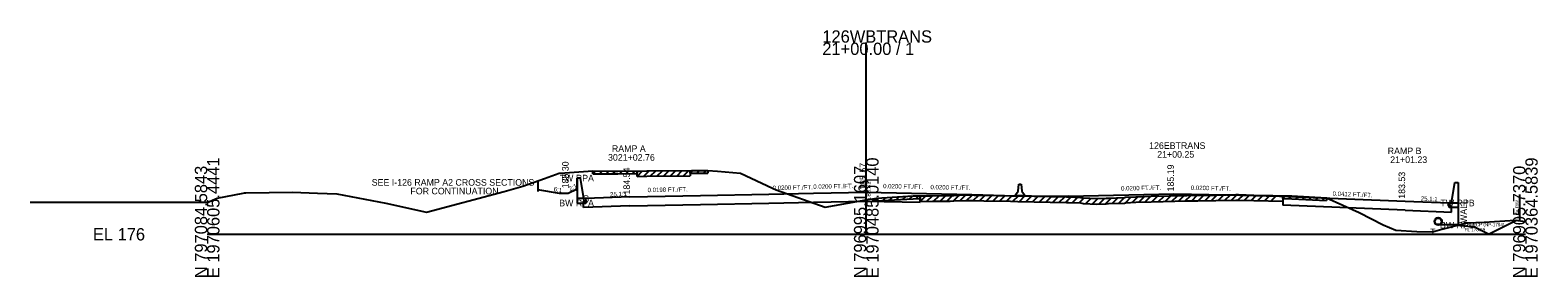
# Model space of a CAD drawing. Extents: x -6494 to 1970605, y -10 to 798140.
# Drawn here: x 959.7 to 1302.8, y 3490.3 to 3546.5 of the extents above; entities that cross this region are included whole.
import ezdxf

# ---------------------------------------------------------------- set-up
doc = ezdxf.new("R2010")
doc.units = 0
for name, color, linetype in [('Default', 7, 'Continuous'), ('RD_EX_SU_Misc_TxCode', 7, 'Continuous'), ('RD_GPK_XS_Cell', 7, 'Continuous'), ('RD_Sketch1', 7, 'Continuous'), ('RD_XS_Base', 7, 'Continuous'), ('RD_XS_Box', 7, 'Continuous'), ('RD_XS_EwShp', 7, 'Continuous'), ('RD_XS_ExGround', 7, 'Continuous'), ('RD_XS_ExPaveRet', 7, 'Continuous'), ('RD_XS_ExRW', 7, 'Continuous'), ('RD_XS_MedBWall', 7, 'Continuous'), ('RD_XS_Misc_Line', 7, 'Continuous'), ('RD_XS_Pave', 7, 'Continuous'), ('RD_XS_PaveOvlay', 7, 'Continuous'), ('RD_XS_PaveShd', 7, 'Continuous'), ('RD_XS_Pipe', 7, 'Continuous'), ('RD_XS_TieSlope', 7, 'Continuous'), ('RD_XS_TX_Elev_EX', 7, 'Continuous'), ('RD_XS_TX_Elev_PR', 7, 'Continuous'), ('RD_XS_TX_Misc', 7, 'Continuous'), ('RD_XS_TX_Notes', 7, 'Continuous'), ('RD_XS_TX_Profile', 7, 'Continuous'), ('RD_XS_TX_Slope', 7, 'Continuous'), ('RD_XS_TX_Station', 7, 'Continuous')]:
    doc.layers.add(name, color=color, linetype=linetype)

msp = doc.modelspace()

# ---------------------------------------------------------------- linework, layer by layer
at = {"layer": 'Default'}
for p, q in [((1184.58, 3509.84), (1184.75, 3511.43)), ((1184.75, 3511.43), (1185.25, 3511.43)), ((1185.25, 3511.43), (1185.42, 3509.84)), ((1184, 3509.01), (1184.58, 3509.84)), ((1184, 3508.76), (1184, 3509.01)), ((1186, 3508.76), (1184, 3508.76)), ((1185.42, 3509.84), (1186, 3509.01)), ((1186, 3509.01), (1186, 3508.76))]:
    msp.add_line(p, q, dxfattribs=at)
at = {"layer": 'RD_GPK_XS_Cell'}
for p, q in [((1150, 3500), (1150, 3543.63)), ((1000, 3500), (1150, 3500)), ((1150, 3500), (1300, 3500))]:
    msp.add_line(p, q, dxfattribs=at)
at = {"layer": 'RD_XS_Base'}
for p, q in [((1085.68, 3507.54), (1086.19, 3507.56)), ((1085.68, 3506.06), (1085.68, 3507.54)), ((1086.19, 3507.56), (1086.19, 3508.12)), ((1096.22, 3506.48), (1112.27, 3506.8)), ((1112.27, 3506.8), (1127.86, 3507.09)), ((1127.86, 3507.09), (1138, 3507.29)), ((1138, 3507.29), (1150, 3507.53)), ((1150, 3507.53), (1162.3, 3507.29)), ((1282.68, 3506.57), (1282.68, 3507.13)), ((1096.22, 3506.48), (1085.68, 3506.06)), ((1272.64, 3505.49), (1244.77, 3506.64)), ((1272.64, 3505.49), (1283.18, 3505.07)), ((1283.18, 3506.55), (1282.68, 3506.57)), ((1283.18, 3505.07), (1283.18, 3506.55))]:
    msp.add_line(p, q, dxfattribs=at)
at = {"layer": 'RD_XS_Box'}
for p, q in [((1084.19, 3509.89), (1084.19, 3508.12)), ((1086.19, 3508.12), (1084.19, 3508.12)), ((1282.68, 3507.13), (1284.69, 3507.13)), ((1284.69, 3507.13), (1284.69, 3502.07))]:
    msp.add_line(p, q, dxfattribs=at)
at = {"layer": 'RD_XS_ExGround'}
msp.add_line((1000, 3507.22), (959.72, 3507.22), dxfattribs=at)
msp.add_lwpolyline([(1000, 3507.22), (1002.26, 3508.25), (1008.17, 3509.39), (1008.49, 3509.45), (1008.8, 3509.46), (1019.44, 3509.56), (1025.15, 3509.37), (1029.55, 3509.23), (1040.69, 3507.06), (1049.95, 3505.01), (1067.56, 3509.72), (1071.87, 3510.93), (1076.76, 3512.68), (1080.11, 3513.88), (1081.37, 3513.96), (1087.79, 3514.41), (1092.12, 3514.4), (1093.46, 3514.39), (1100.05, 3514.45), (1110.25, 3514.53), (1113.17, 3514.54), (1113.95, 3514.54), (1116.14, 3514.37), (1121.36, 3513.92), (1128.7, 3510.51), (1129.47, 3510.15), (1140.62, 3506.14), (1150, 3507.81), (1152.3, 3508.21), (1153.51, 3508.3), (1160.67, 3508.72), (1165.06, 3508.77), (1169.07, 3508.82), (1169.93, 3508.85), (1172.67, 3508.96), (1174.58, 3508.93), (1176.76, 3508.9), (1182.83, 3508.78), (1184.52, 3508.75), (1195.6, 3508.52), (1196.08, 3508.51), (1198.77, 3508.39), (1199.03, 3508.3), (1199.34, 3508.29), (1202.44, 3508.13), (1204.61, 3508.21), (1205.15, 3508.23), (1208.76, 3508.34), (1209, 3508.44), (1211.32, 3508.54), (1214.82, 3508.64), (1222.98, 3508.85), (1225.48, 3508.88), (1229.52, 3508.94), (1234.07, 3509.03), (1234.75, 3509.04), (1238.22, 3508.93), (1246.86, 3508.72), (1254.77, 3508.33), (1262.18, 3504.96), (1267.62, 3502.14), (1270.5, 3500.95), (1275.27, 3500.65), (1278.87, 3500.56), (1280.49, 3500.99), (1286.77, 3502.6), (1290.64, 3502.79), (1297.67, 3503.21), (1300, 3502.92)], dxfattribs=at)
at = {"layer": 'RD_XS_ExPaveRet'}
for p, q in [((1087.79, 3513.78), (1087.79, 3514.41)), ((1087.79, 3513.78), (1092.12, 3513.77)), ((1092.12, 3513.77), (1093.46, 3513.77)), ((1093.46, 3513.77), (1097.83, 3513.81)), ((1097.83, 3513.18), (1097.83, 3514.43)), ((1097.83, 3514.43), (1097.83, 3513.81)), ((1109.93, 3514.53), (1109.93, 3513.28)), ((1109.93, 3513.9), (1109.93, 3514.53)), ((1109.93, 3513.9), (1110.25, 3513.91)), ((1110.25, 3513.91), (1113.17, 3513.92)), ((1113.17, 3513.92), (1113.95, 3513.92)), ((1113.95, 3514.54), (1113.95, 3513.92)), ((1097.83, 3513.18), (1100.05, 3513.2)), ((1100.05, 3513.2), (1109.93, 3513.28)), ((1152.3, 3507.59), (1152.3, 3508.21)), ((1152.3, 3507.59), (1153.51, 3507.67)), ((1153.51, 3507.67), (1160.67, 3508.1)), ((1160.67, 3508.1), (1162.3, 3508.12)), ((1162.3, 3507.49), (1162.3, 3508.74)), ((1162.3, 3508.74), (1162.3, 3508.12)), ((1162.3, 3507.49), (1165.06, 3507.52)), ((1165.06, 3507.52), (1169.07, 3507.57)), ((1169.07, 3507.57), (1169.93, 3507.6)), ((1169.93, 3507.6), (1172.67, 3507.71)), ((1172.67, 3507.71), (1174.58, 3507.68)), ((1174.58, 3507.68), (1176.76, 3507.65)), ((1176.76, 3507.65), (1182.83, 3507.53)), ((1182.83, 3507.53), (1184.52, 3507.5)), ((1184.52, 3507.5), (1195.6, 3507.27)), ((1195.6, 3507.27), (1196.08, 3507.26)), ((1196.08, 3507.26), (1198.77, 3507.14)), ((1198.77, 3507.14), (1199.03, 3507.05)), ((1199.03, 3507.05), (1199.34, 3507.04)), ((1199.34, 3507.04), (1202.44, 3506.88)), ((1202.44, 3506.88), (1204.61, 3506.96)), ((1204.61, 3506.96), (1205.15, 3506.98)), ((1205.15, 3506.98), (1208.76, 3507.09)), ((1208.76, 3507.09), (1209, 3507.19)), ((1209, 3507.19), (1211.32, 3507.29)), ((1211.32, 3507.29), (1214.82, 3507.39)), ((1214.82, 3507.39), (1222.98, 3507.6)), ((1222.98, 3507.6), (1225.48, 3507.63)), ((1225.48, 3507.63), (1229.52, 3507.69)), ((1229.52, 3507.69), (1234.07, 3507.78)), ((1234.07, 3507.78), (1234.75, 3507.79)), ((1234.75, 3507.79), (1238.22, 3507.68)), ((1238.22, 3507.68), (1244.77, 3507.52)), ((1244.77, 3508.77), (1244.77, 3507.52)), ((1244.77, 3508.14), (1244.77, 3508.77)), ((1244.77, 3508.14), (1246.86, 3508.09)), ((1246.86, 3508.09), (1254.77, 3507.7)), ((1254.77, 3508.33), (1254.77, 3507.7))]:
    msp.add_line(p, q, dxfattribs=at)
at = {"layer": 'RD_XS_ExRW'}
msp.add_line((1298.65, 3509.09), (1298.65, 3503.09), dxfattribs=at)
at = {"layer": 'RD_XS_MedBWall'}
for p, q in [((1084.19, 3509.89), (1084.19, 3512.79)), ((1084.94, 3512.79), (1084.19, 3512.79)), ((1084.19, 3512.79), (1084.19, 3507.12)), ((1085.69, 3508.12), (1084.94, 3512.79)), ((1283.18, 3507.13), (1283.93, 3511.8)), ((1283.93, 3511.8), (1284.68, 3511.8)), ((1284.68, 3511.8), (1284.68, 3506.13)), ((1084.19, 3507.12), (1086.19, 3507.12)), ((1086.19, 3508.12), (1085.69, 3508.12)), ((1086.19, 3507.12), (1086.19, 3508.12)), ((1282.68, 3506.13), (1282.68, 3507.13)), ((1282.68, 3507.13), (1283.18, 3507.13)), ((1284.68, 3506.13), (1282.68, 3506.13))]:
    msp.add_line(p, q, dxfattribs=at)
at = {"layer": 'RD_XS_Misc_Line'}
for p, q in [((1087.79, 3513.78), (1088.42, 3514.41)), ((1089.3, 3513.78), (1089.92, 3514.4)), ((1090.8, 3513.78), (1091.43, 3514.4)), ((1092.31, 3513.77), (1092.93, 3514.4)), ((1093.81, 3513.77), (1094.45, 3514.4)), ((1095.32, 3513.78), (1095.95, 3514.42)), ((1096.83, 3513.8), (1097.46, 3514.43)), ((1097.83, 3513.18), (1099.1, 3514.44)), ((1099.34, 3513.19), (1100.6, 3514.46)), ((1100.84, 3513.21), (1102.11, 3514.47)), ((1102.35, 3513.22), (1103.62, 3514.48)), ((1103.86, 3513.23), (1105.12, 3514.49)), ((1105.36, 3513.24), (1106.63, 3514.5)), ((1106.87, 3513.25), (1108.13, 3514.51)), ((1108.38, 3513.27), (1109.64, 3514.53)), ((1109.93, 3513.9), (1110.56, 3514.53)), ((1111.44, 3513.91), (1112.07, 3514.54)), ((1112.94, 3513.92), (1113.57, 3514.54)), ((1152.3, 3507.59), (1152.97, 3508.26)), ((1153.8, 3507.69), (1154.47, 3508.35)), ((1155.31, 3507.78), (1155.98, 3508.44)), ((1156.82, 3507.87), (1157.49, 3508.53)), ((1158.32, 3507.96), (1158.99, 3508.62)), ((1159.83, 3508.05), (1160.5, 3508.71)), ((1161.34, 3508.11), (1161.97, 3508.74)), ((1162.3, 3507.49), (1163.57, 3508.75)), ((1163.81, 3507.51), (1165.07, 3508.77)), ((1165.31, 3507.52), (1166.58, 3508.79)), ((1166.82, 3507.54), (1168.09, 3508.81)), ((1168.33, 3507.56), (1169.61, 3508.84)), ((1169.83, 3507.59), (1171.14, 3508.9)), ((1171.34, 3507.66), (1172.65, 3508.96)), ((1172.84, 3507.71), (1174.08, 3508.94)), ((1174.35, 3507.69), (1175.59, 3508.92)), ((1175.86, 3507.66), (1177.09, 3508.89)), ((1177.36, 3507.64), (1178.59, 3508.86)), ((1178.87, 3507.61), (1180.1, 3508.83)), ((1180.38, 3507.58), (1181.61, 3508.8)), ((1181.88, 3507.55), (1183.11, 3508.77)), ((1183.39, 3507.52), (1184.62, 3508.75)), ((1184.89, 3507.49), (1186.12, 3508.72)), ((1186.4, 3507.46), (1187.63, 3508.69)), ((1187.91, 3507.43), (1189.14, 3508.66)), ((1189.41, 3507.4), (1190.64, 3508.63)), ((1190.92, 3507.37), (1192.15, 3508.59)), ((1192.43, 3507.34), (1193.66, 3508.56)), ((1193.93, 3507.31), (1195.16, 3508.53)), ((1195.44, 3507.28), (1196.65, 3508.49)), ((1196.95, 3507.22), (1198.15, 3508.42)), ((1198.45, 3507.16), (1199.58, 3508.28)), ((1199.96, 3507.01), (1201.15, 3508.2)), ((1201.46, 3506.93), (1202.68, 3508.14)), ((1202.97, 3506.9), (1204.27, 3508.2)), ((1204.48, 3506.96), (1205.77, 3508.25)), ((1205.98, 3507), (1207.28, 3508.3)), ((1207.49, 3507.05), (1208.8, 3508.36)), ((1209, 3507.19), (1210.31, 3508.5)), ((1210.5, 3507.26), (1211.81, 3508.56)), ((1212.01, 3507.31), (1213.3, 3508.6)), ((1213.51, 3507.35), (1214.8, 3508.64)), ((1215.02, 3507.39), (1216.31, 3508.68)), ((1216.53, 3507.43), (1217.82, 3508.71)), ((1218.03, 3507.47), (1219.32, 3508.75)), ((1219.54, 3507.51), (1220.83, 3508.79)), ((1221.05, 3507.55), (1222.33, 3508.83)), ((1222.55, 3507.59), (1223.83, 3508.86)), ((1224.06, 3507.61), (1225.33, 3508.88)), ((1225.57, 3507.63), (1226.84, 3508.9)), ((1227.07, 3507.65), (1228.35, 3508.92)), ((1228.58, 3507.67), (1229.85, 3508.95)), ((1230.08, 3507.7), (1231.36, 3508.97)), ((1231.59, 3507.73), (1232.87, 3509)), ((1233.1, 3507.76), (1234.38, 3509.03)), ((1234.6, 3507.79), (1235.83, 3509)), ((1236.11, 3507.75), (1237.33, 3508.96)), ((1237.62, 3507.7), (1238.84, 3508.91)), ((1239.12, 3507.66), (1240.35, 3508.88)), ((1240.63, 3507.62), (1241.85, 3508.84)), ((1242.14, 3507.58), (1243.36, 3508.8)), ((1244.77, 3508.14), (1245.39, 3508.76)), ((1246.28, 3508.11), (1246.89, 3508.72)), ((1247.79, 3508.05), (1248.38, 3508.64)), ((1249.29, 3507.97), (1249.89, 3508.57)), ((1250.8, 3507.9), (1251.4, 3508.49)), ((1252.31, 3507.82), (1252.9, 3508.42)), ((1253.81, 3507.75), (1254.41, 3508.34))]:
    msp.add_line(p, q, dxfattribs=at)
at = {"layer": 'RD_XS_Pave'}
for p, q in [((1096.22, 3508.52), (1112.27, 3508.84)), ((1127.86, 3509.13), (1138, 3509.33)), ((1138, 3509.33), (1150, 3509.57)), ((1150, 3509.57), (1174, 3509.09)), ((1196.02, 3508.71), (1220.02, 3509.19)), ((1220.02, 3509.19), (1232.02, 3508.95)), ((1232.02, 3508.95), (1244.02, 3508.71)), ((1244.02, 3508.71), (1272.64, 3507.53))]:
    msp.add_line(p, q, dxfattribs=at)
at = {"layer": 'RD_XS_PaveOvlay'}
for p, q in [((1162.3, 3508.74), (1165.06, 3508.77)), ((1162.3, 3508.74), (1162.3, 3507.29)), ((1165.06, 3508.77), (1169.07, 3508.82)), ((1169.07, 3508.82), (1169.93, 3508.85)), ((1169.93, 3508.85), (1172.67, 3508.96)), ((1172.67, 3508.96), (1174.58, 3508.93)), ((1174.58, 3508.93), (1176.76, 3508.9)), ((1176.76, 3508.9), (1182.83, 3508.78)), ((1182.83, 3508.78), (1184.52, 3508.75)), ((1184.52, 3508.75), (1195.6, 3508.52)), ((1195.6, 3508.52), (1196.08, 3508.51)), ((1196.08, 3508.51), (1198.77, 3508.39)), ((1198.77, 3508.39), (1199.03, 3508.3)), ((1199.03, 3508.3), (1199.34, 3508.29)), ((1199.34, 3508.29), (1202.44, 3508.13)), ((1202.44, 3508.13), (1204.61, 3508.21)), ((1204.61, 3508.21), (1205.15, 3508.23)), ((1205.15, 3508.23), (1208.76, 3508.34)), ((1208.76, 3508.34), (1209, 3508.44)), ((1209, 3508.44), (1211.32, 3508.54)), ((1211.32, 3508.54), (1214.82, 3508.64)), ((1214.82, 3508.64), (1222.98, 3508.85)), ((1222.98, 3508.85), (1225.48, 3508.88)), ((1225.48, 3508.88), (1229.52, 3508.94)), ((1229.52, 3508.94), (1234.07, 3509.03)), ((1234.07, 3509.03), (1234.75, 3509.04)), ((1234.75, 3509.04), (1238.22, 3508.93)), ((1238.22, 3508.93), (1244.77, 3508.77)), ((1244.77, 3508.77), (1244.77, 3506.64))]:
    msp.add_line(p, q, dxfattribs=at)
at = {"layer": 'RD_XS_PaveShd'}
for p, q in [((1096.22, 3508.52), (1086.19, 3508.12)), ((1112.27, 3508.84), (1127.86, 3509.13)), ((1174, 3509.09), (1184, 3508.76)), ((1191.21, 3508.61), (1184, 3508.76)), ((1196.02, 3508.71), (1191.21, 3508.61)), ((1272.64, 3507.53), (1282.68, 3507.13))]:
    msp.add_line(p, q, dxfattribs=at)
at = {"layer": 'RD_XS_Pipe'}
msp.add_line((1280.67, 3502.19), (1285.67, 3502.19), dxfattribs=at)
for radius in [0.85, 0.75]:
    msp.add_circle((1280.17, 3502.94), radius, dxfattribs=at)
at = {"layer": 'RD_XS_TieSlope'}
for p, q in [((1075.24, 3512.13), (1075.24, 3509.71)), ((1084.19, 3510.3), (1082.19, 3509.3)), ((1080.19, 3509.3), (1075.24, 3510.12)), ((1082.19, 3509.3), (1080.19, 3509.3)), ((1284.69, 3502.07), (1288.46, 3501.69)), ((1288.46, 3501.69), (1291.77, 3500.04)), ((1297.96, 3503.14), (1291.77, 3500.04))]:
    msp.add_line(p, q, dxfattribs=at)

# ---------------------------------------------------------------- texts
at = {"layer": 'RD_EX_SU_Misc_TxCode'}
msp.add_text('G', height=1.5, dxfattribs=at).set_placement((1085.44, 3507.37))
at = {"layer": 'RD_GPK_XS_Cell'}
for s, p in [('126WBTRANS', (1140, 3543.63)), ('21+00.00 / 1', (1140, 3540.83)), ('EL 176', (974, 3498.6))]:
    msp.add_text(s, height=2.8, dxfattribs=at).set_placement(p)
for s, p in [('E 1970605.4441', (1002.8, 3490)), ('E 1970485.0140', (1152.8, 3490)), ('E 1970364.5839', (1302.8, 3490)), ('N 797084.5843', (1000, 3490)), ('N 796995.1607', (1150, 3490)), ('N 796905.7370', (1300, 3490))]:
    msp.add_text(s, height=2.8, rotation=90, dxfattribs=at).set_placement(p)
at = {"layer": 'RD_Sketch1'}
msp.add_text('T', height=1.5, dxfattribs=at).set_placement((1278.32, 3499.81))
at = {"layer": 'RD_XS_EwShp'}
for s, p in [('TW RPA', (1080.22, 3512.04)), ('BW RPA', (1080.12, 3506.37)), ('TW RPB', (1280.66, 3506.38)), ('BW RPB', (1280.56, 3501.32))]:
    msp.add_text(s, height=1.5, dxfattribs=at).set_placement(p)
at = {"layer": 'RD_XS_ExRW'}
msp.add_text('Ex. R/W ', height=0.65, rotation=90, dxfattribs=at).set_placement((1298.4, 3504.47))
at = {"layer": 'RD_XS_Pipe'}
for s, p in [('18" RCP (NP-1794)', (1286.17, 3501.81)), ('FL 178.19', (1286.17, 3500.69))]:
    msp.add_text(s, height=0.75, dxfattribs=at).set_placement(p)
at = {"layer": 'RD_XS_TX_Elev_EX'}
msp.add_text('183.81', height=1, rotation=90, dxfattribs=at).set_placement((1151, 3507.81))
at = {"layer": 'RD_XS_TX_Elev_PR'}
for s, p in [(' 184.54', (1096.22, 3508.5)), (' 185.57', (1150, 3509.57)), (' 185.19', (1220.02, 3509.19)), (' 183.53', (1272.64, 3507.53))]:
    msp.add_text(s, height=1.5, rotation=90, dxfattribs=at).set_placement(p)
at = {"layer": 'RD_XS_TX_Misc'}
msp.add_text('185.30', height=1.5, rotation=90, dxfattribs=at).set_placement((1082.27, 3510.46))
at = {"layer": 'RD_XS_TX_Notes'}
for s, p in [('SEE I-126 RAMP A2 CROSS SECTIONS', (1037.45, 3511.06)), ('FOR CONTINUATION', (1046.26, 3509.09))]:
    msp.add_text(s, height=1.5, dxfattribs=at).set_placement(p)
msp.add_text('WALL', height=1.5, rotation=90, dxfattribs=at).set_placement((1286.7, 3502.57))
at = {"layer": 'RD_XS_TX_Profile'}
msp.add_text('25.1:1', height=1, rotation=357.7188, dxfattribs=at).set_placement((1276.19, 3507.64))
at = {"layer": 'RD_XS_TX_Slope'}
for s, rotation, p in [('6:1', 350.5377, (1078.8, 3509.83)), ('2:1', 26.5651, (1082.59, 3509.81)), ('0.0198 FT./FT.', 1.1328, (1100.24, 3509.58)), ('0.0200 FT./FT.', 1.1458, (1128.71, 3510.06)), ('0.0200 FT./FT.', 1.143, (1137.95, 3510.33)), ('0.0200 FT./FT.', 358.8542, (1153.83, 3510.49)), ('0.0200 FT./FT.', 358.8542, (1164.6, 3510.26)), ('0.0200 FT./FT.', 1.1456, (1208, 3509.95)), ('0.0200 FT./FT.', 358.8541, (1223.85, 3510.11)), ('25.1:1', 2.2832, (1091.72, 3508.59)), ('0.0412 FT./FT.', 357.6386, (1256.11, 3508.78))]:
    msp.add_text(s, height=1, rotation=rotation, dxfattribs=at).set_placement(p)
at = {"layer": 'RD_XS_TX_Station'}
for s, p in [('126EBTRANS', (1214.37, 3519.44)), ('3021+02.76', (1091.23, 3516.75)), ('RAMP A', (1092.11, 3518.75)), ('21+00.25', (1216.22, 3517.44)), ('RAMP B', (1268.67, 3518.24)), ('21+01.23', (1269.24, 3516.24))]:
    msp.add_text(s, height=1.5, dxfattribs=at).set_placement(p)

doc.saveas('drawing.dxf')
